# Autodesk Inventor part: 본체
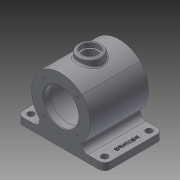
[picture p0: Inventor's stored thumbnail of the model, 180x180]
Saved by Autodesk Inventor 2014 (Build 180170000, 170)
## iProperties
Company: 한국ATC센터
Created: 2014-08
Part Number: 본체
Document SubType Name: Modeling
Designer: KYOUNG IL JANG
Density: 1 g/cm^3
Material: 일반
Mass: 1211.76 g
Surface Area: 1019.41 cm^2
Volume: 447.145 cm^3
Appearance: 기본값
Author: KYOUNG IL JANG
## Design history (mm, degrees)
sketch "스케치1"
  geometry: L1 (-50, 0)-(50, 0); L2 (-36.062, 36.062)-(36.062, 36.062); L3 (36.062, 36.062)-(36.062, -36.062); L4 (36.062, -36.062)-(-36.062, -36.062); L5 (-36.062, -36.062)-(-36.062, 36.062); A1 r 53.623 centre (-3.623, 0) between (36.062, -36.062) and (36.062, 36.062); A2 r 53.623 centre (3.623, 0) between (-36.062, 36.062) and (-36.062, -36.062); A3 r 53.623 centre (0, -3.623) between (36.062, 36.062) and (-36.062, 36.062); A4 r 53.623 centre (0, 3.623) between (-36.062, -36.062) and (36.062, -36.062); 4 further points
  constraints: 11 point on circle, 10 end point, 5 coincident, 4 centre point, 4 horizontal alignment, 3 equal radius, 2 horizontal, 2 parallel, 2 perpendicular, 1 midpoint
  dimensions: "d83" = 51 distance of L2.end point (0, 0); "d84" = 100 distance of L1.end L1.start
extrude "돌출1" new body sketch "스케치1" stored distance "d9" = 100; taper "d10" = 0 deg
node "작업 평면1"
sketch "스케치2"
  geometry: L1 (75, 50)-(-75, 50); L2 (-75, 50)-(-75, -50); L3 (-75, -50)-(75, -50); L4 (75, -50)-(75, 50); 4 further points
  constraints: 8 end point, 3 midpoint, 2 parallel, 2 vertical alignment, 1 horizontal, 1 horizontal alignment, 1 perpendicular
  dimensions: "d14" = 150 distance of L2.end L3.end; "d82" = 100 distance of L1.end L2.end
extrude "돌출2" join sketch "스케치2" distance "d15" = 12; taper "d16" = 0 deg
node "작업 평면3"
  node "작업 평면4"
sketch "스케치3"
  geometry: C1 r 20 at (0, 0); 1 further point
  constraints: 2 coincident, 1 centre point
  dimensions: "d19" = 40 diameter of C1
extrude "돌출3" join sketch "스케치3" stored distance "d23" = 12; taper "d24" = 0 deg
node "작업 평면6"
  node "작업 평면5"
sketch "스케치4"
  geometry: C1 r 37.5 at (0, 0); 1 further point
  constraints: 1 centre point, 1 coincident
  dimensions: "d25" = 75 diameter of C1
extrude "돌출4" cut sketch "스케치4" stored distance "d26" = 76; taper "d27" = 0 deg
sketch "스케치5"
  geometry: C1 r 30 at (0, 0); 1 further point
  constraints: 1 centre point, 1 coincident
  dimensions: "d28" = 60 diameter of C1
extrude "돌출5" cut sketch "스케치5" stored distance "d29" = 116; taper "d30" = 0 deg
hole "구멍1" diameter "d33" = 25; stored, may be unused: countersink angle "d37" = 90 deg, drill point angle "d39" = 0 deg; dims "d31" = 10, "d32" = 10, "d34" = 6, "d35" = 30, "d36" = 8, "d38" = 40
sketch "스케치6"
  geometry: L1 (-75, -50)-(-75, 50) reference; L2 (-75, 50)-(75, 50) reference; L3 (75, -50)-(-75, -50) reference; L4 (75, 50)-(75, -50) reference; L5 (0, -50)-(0, 50); L6 (-75, 0)-(75, 0); L7 (-63, -38)-(63, 38); C1 r 5.5 at (-63, -38); C2 r 5.5 at (-63, 38); C3 r 5.5 at (63, -38); C4 r 5.5 at (63, 38); 2 further points
  constraints: 6 end point, 6 midpoint, 4 centre point, 2 equal radius, 2 horizontal alignment, 2 vertical alignment
  dimensions: "d49" = 11 diameter of C1; "d50" = 11 diameter of C2; "d100" = 12 distance from line of L2 C2.centre; "d101" = 12 distance from line of C2.centre L1
extrude "돌출6" cut sketch "스케치6" distance "d53" = 116; taper "d54" = 0 deg
sketch "스케치8"
  geometry: L1 (75, 50)-(75, -50) reference; 2 further points
  constraints: 1 horizontal alignment, 1 other
  dimensions: "d55" = 12 distance from line of L1 point (63, 0)
feature "엠보싱1" sketch "스케치8" dims "d57" = 1, "d58" = 0, "d83" = 51, "d84" = 100
fillet "모깎기2" dims "d60" = 10
fillet "모깎기5" dims "d63" = 10
fillet "모깎기7" dims "d65" = 3
sketch "스케치9"
  geometry: L1 (0, 0)-(-28.284, 28.284); L2 (0, 0)-(0, 40); C1 r 30 at (0, 0) reference; A1 r 40 centre (0, 0) between (-28.284, 28.284) and (0, 40); 1 further point
  constraints: 4 end point, 2 coincident, 2 point on circle, 1 centre point, 1 vertical
  dimensions: "d66" = 80 diameter of A1; "d67" = 45 deg angle of L1 L2
hole "M4" sketch "스케치9" at (-28.284, 28.284) diameter "d68" = 3.242; stored, may be unused: countersink angle "d72" = 90 deg, drill point angle "d74" = 118 deg; dims "d69" = 8, "d70" = 30, "d71" = 8, "d73" = 10
fillet "모깎기8" dims "d78" = 3
chamfer "모따기1" distance "d79" = 1; stored, may be unused: second distance "d80" = 2, angle "d81" = 45 deg
node "솔리드1"
pattern_circular "원형 패턴1" dims angle "d76" = 360 deg
mirror "대칭1"
